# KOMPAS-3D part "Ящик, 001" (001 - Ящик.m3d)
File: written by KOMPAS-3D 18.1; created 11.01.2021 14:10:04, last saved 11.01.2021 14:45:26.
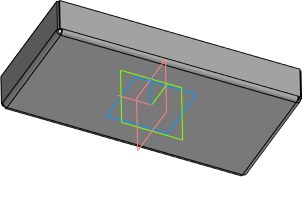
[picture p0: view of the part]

Document properties: Полное имя файла: D:\Ящик\001 - Ящик.m3d

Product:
- Part/product: Ящик  | designation 001
    Масса: 0.424246
    source file: Развертки.cdw

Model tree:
1. Эскиз:1
2. Листовое тело:1
     Расстояние 1 = 10; Радиус сгиба = 2
3. Сгиб:1  (with: Листовое тело:1)
     Радиус сгиба = 2; Коэффициент = 0.4; Величина сгиба = 10; Радиус сгиба = 2; Коэффициент = 0.4; Величина сгиба = 10; Радиус сгиба = 2; Коэффициент = 0.4; Величина сгиба = 10; Радиус сгиба = 2; Коэффициент = 0.4; Величина сгиба = 10; Толщина листового тела = 1.5; Ширина освобождения сгиба = 0.5; Ширина сгиба = 200; Длина 1 = 30; Длина 2 = 10
4. Развертка  (with: Листовое тело:1)

Referenced files in D:\Ящик\: Сборка.a3d||L, Сборка.a3d||K, Сборка.a3d||T_met, Сборка.a3d||R_gib
Referenced files in D:\Временные файлы КОМПАСа\Ящик_мойки\: Сборка.a3d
